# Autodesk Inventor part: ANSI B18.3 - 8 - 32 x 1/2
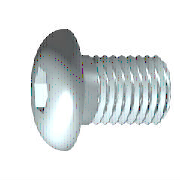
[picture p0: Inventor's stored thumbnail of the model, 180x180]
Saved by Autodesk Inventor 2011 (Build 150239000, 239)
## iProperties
IsCustomPart: 0
Created: 2008-02
Part Number: ANSI B18.3 - 8 - 32 x 1/2
Material: Steel, Mild
Description: Hexagon Socket Button Head Cap Screw
Document SubType Name: Modeling
Standard: ANSI B18.3
Standard Revision: 2003
Standards Organization: ANSI
Language: en-US
Size Designation: 8 - 32 x 1/2
Categories: <MemberInstance><Categories><Category DisplayName="Fasteners" InternalName="e4da775c-781d-43d5-af7c-5136215cf5a6" Mnemonic="FSTN"><Category DisplayName="Bolts"
Density: 1 g/cm^3
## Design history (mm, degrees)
body "Solid1"
workplane "Work Plane1"
fillet "Fillet2" dims "d30" = 0.1 (= R)
revolve "Body" stored, may be unused: angle "d10" = 90 deg
sketch "Sketch2"
  geometry: L1 (0, -5.547)-(0, 5.547) reference; L2 (-5.547, 0)-(5.547, 0) reference; L3 (1.378, 0)-(0.689, -1.194); L4 (0.689, -1.194)-(-0.689, -1.194); L5 (-0.689, -1.194)-(-1.378, 0); L6 (-1.378, 0)-(-0.689, 1.194); L7 (-0.689, 1.194)-(0.689, 1.194); L8 (0.689, 1.194)-(1.378, 0); 2 further points
  constraints: 12 end point, 1 coincident, 1 horizontal alignment, 1 point on line, 12 other
extrude "Slot" join sketch "Sketch2" stored distance "d11" = 10; taper "d12" = 0 deg
fillet "Fillet1" dims "d17" = 1.9558 (= RR)
feature "Thread" dims "d13" = 11.10976 (= GEL), "d14" = 0
chamfer "Chamfer1" distance "d15" = 0.48692 (= -0.5 x SPD + 0.5 x GD); stored, may be unused: second distance "d16" = 0.48692 (= GUL), angle "d27" = 45 deg
sketch "Sketch1"
  geometry: L1 (-0.093, 0)-(12.7, 0); L2 (12.7, 0)-(12.7, 2.083); L3 (12.7, 2.083)-(1.59, 2.083); L4 (1.59, 2.083)-(0, 2.083); L5 (0, 2.083)-(0, 2.083); L6 (0, 2.083)-(0, 3.962); L7 (0, 3.962)-(-2.21, 3.962); L8 (-2.21, 3.962)-(-2.21, 1.378); L9 (-2.21, 1.378)-(-0.889, 1.378); L10 (-0.889, 1.378)-(-0.093, 0); L11 (-5.192, 0)-(15.682, 0) reference; L12 (0, -0.792)-(0, 4.755) reference; L13 (1.59, 2.083)-(0, 2.083)
  constraints: 22 end point, 6 parallel, 2 collinear, 2 perpendicular, 1 horizontal, 1 point on line
  dimensions: "d1" = 11.10976 distance from line of L3.end L2 (= GEL); "d2" = 1.59014 distance of L4.end L3.end (computed from GAL); "d3" = 2.2098 distance between parallel lines of L8 L6 (= KOH); "d4" = 1.3208 distance of L8.end L9.end (= INTI); "d5" = 60 deg angle of L10 L1; "d6" = 4.1656 diameter of L3 L1 (= GD); "d7" = 4.1656 diameter of L5 L1 (= BDM); "d8" = 2.75696 diameter of L9 L1 (= 1.1547 x SW); "d9" = 7.9248 diameter of L7 L1 (= KOD); "d26" = 12.7 distance between parallel lines of L12 L2 (= NLG)
other parameters: "GD" = 4.1656 (= NND) [user parameter; used in 2 equation terms], "NLG" = 12.7 [user parameter; used in 1 equation term], "GEL" = 11.10976 [user parameter; used in 2 equation terms], "KOD" = 7.9248 [user parameter; used in 1 equation term], "KOH" = 2.2098 [user parameter; used in 1 equation term], "INTI" = 1.3208 [user parameter; used in 1 equation term], "GAL" = 1.59004 [user parameter; used in 1 equation term], "GUL" = 0.48692 [user parameter; used in 1 equation term], "BDM" = 4.1656 (= NND) [user parameter; used in 1 equation term], "SW" = 2.3876 [user parameter; used in 1 equation term], "RR" = 1.9558 [user parameter; used in 1 equation term], "SPD" = 3.19176 [user parameter; used in 2 equation terms], "d19" = 0, "d28" = 0, "d29" = 0, "R" = 0.1 [user parameter; used in 1 equation term], "TOA" = 30 deg [user parameter], "GD1" = 3.19176 (= SPD) [user parameter], "THREADDIA" = 4.1656 [user parameter], "PTC" = 0.79375 (computed from TPU) [user parameter], "KOH1" = 0.381 [user parameter], "NND" = 4.1656 [user parameter; used in 2 equation terms], "E0" = 2.75768 [user parameter]
